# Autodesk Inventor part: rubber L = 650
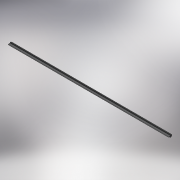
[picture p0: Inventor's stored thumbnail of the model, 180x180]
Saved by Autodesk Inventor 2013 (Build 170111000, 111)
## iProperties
Shininess: 20.0
Length Units: 11269
Angle Units: 11279
Time Units: 11290
Mass Units: 11283
Length Display Precision: 3
Angle Display Precision: 2
Created: 2002-03
Part Number: rubber L = 650
Document SubType Name: Modeling
Designer: =<Author>
Material: Silicone
Density: 1.25 g/cm^3
Description: =<Part Number>
Density: 0.0
Volumn: 0.0
Area: 0.0
PropertySet Name: Model Information
Control State: 0
Master: False
Checked Out: True
Checked Out Date: 2008-10-15
Last Check In Date: 2008-10-15
Author: LAlexey
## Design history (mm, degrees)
sketch "Sketch1"
  geometry: L1 (-7, -1.5)-(-8.5, -1.5); L2 (-7, -1.5)-(-7, -2.5); L3 (-7, 1.5)-(-7, 2.5); L4 (-7, 1.5)-(-8.5, 1.5); L5 (-8.5, 1.5)-(-8.5, 5); L6 (-8.5, 5)-(-10, 5); L7 (-10, 3)-(-10, 5); L8 (-10, 3)-(-11.5, 3); L9 (-11.5, 1)-(-11.5, 3); L10 (-11.5, 1)-(-12.5, 1); L11 (-12.5, 1)-(-12.5, 3); L12 (-12.5, 3)-(-14, 3); L13 (-14, -3)-(-14, 3); L14 (-12.5, -3)-(-14, -3); L15 (-12.5, -3)-(-12.5, -1); L16 (-11.5, -1)-(-12.5, -1); L17 (-11.5, -3)-(-11.5, -1); L18 (-10, -3)-(-11.5, -3); L19 (-10, -5)-(-10, -3); L20 (-8.5, -5)-(-10, -5); L21 (-8.5, -1.5)-(-8.5, -5); A1 r 16.028 centre (1.744, -15.933) between (0, 0) and (-7, -2.5); A2 r 16.028 centre (1.744, 15.933) between (-7, 2.5) and (0, 0)
  constraints: 42 end point, 11 vertical, 10 horizontal, 7 collinear, 4 point on circle, 2 centre point, 1 other
extrude "ExtrusionBlind1" new body sketch "Sketch1" distance "d0" = 650; taper "d1" = 0 deg
body "Solid1"
